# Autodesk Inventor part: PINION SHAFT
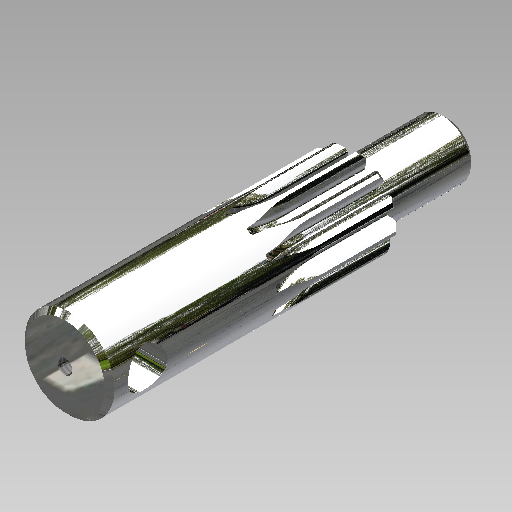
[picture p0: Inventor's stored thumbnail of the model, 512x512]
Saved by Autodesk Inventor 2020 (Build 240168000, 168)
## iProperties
Part Number: PINION SHAFT
Document SubType Name: Modeling
Created: 2003-10
Designer: Autodesk, Inc.
Manufacturer: Standard
Standards Organization: Custom
Mass: 507.092 g
Surface Area: 152.229 cm^2
Volume: 64.5977 cm^3
Density: 7.85 g/cm^3
Material: Steel, High Strength Low Alloy
Appearance: Chrome - Polished
Control State: 0
Master: False
Checked Out: False
Shininess: 64.0
Length Units: 11269
Angle Units: 11279
Time Units: 11290
Mass Units: 11283
Length Display Precision: 3
Angle Display Precision: 2
Compacted: True
Density: 0.0
Volumn: 0.0
Area: 0.0
PropertySet Name: Model Information
Author: Autodesk, Inc.
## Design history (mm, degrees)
sketch "Sketch1" dims "d4" = 6.7945 (= Big_R), "d5" = 5.54567 (= 2 x little_r)
  geometry: L1 (0, 12.7)-(5.815, 12.7); L2 (5.815, 12.7)-(5.815, 14.817); L3 (5.815, 14.817)-(0, 14.817); L4 (0, 14.817)-(0, 12.7); L5 (-8.163, 9.729)-(5.815, 14.817); L6 (0, 0)-(0, 10.251); L7 (0, 11.934)-(0, 12.7); L8 (0, 11.934)-(0, 10.251); L9 (-0.191, 11.933)-(-0.184, 10.731); L10 (0, 0)-(1.934, 14.69); L11 (0, 0)-(-1.338, 10.163); L12 (0, 0)-(3.923, 9.471); L13 (3.273, 11.477)-(2.955, 10.318); L14 (-0.181, 10.249)-(-0.184, 10.731); A1 r 12.7 centre (0, 0) between (0, 12.7) and (-8.163, 9.729); A2 r 14.817 centre (0, 0) between (0, 14.817) and (1.934, 14.69); A3 r 11.934 centre (0, 0) between (0, 11.934) and (6.294, 10.14); A4 r 10.251 centre (0, 0) between (0, 10.251) and (-0.181, 10.249); A5 r 6.795 centre (6.294, 10.14) between (1.365, 14.817) and (0, 12.7); A6 r 2.773 centre (2.568, 11.654) between (0, 12.7) and (-0.191, 11.933); A7 r 10.251 centre (0, 0) between (-0.651, 10.23) and (-1.338, 10.163); A8 r 0.498 centre (-0.682, 10.728) between (-0.651, 10.23) and (-0.184, 10.731); A9 r 10.251 centre (0, 0) between (3.923, 9.471) and (3.276, 9.713); A10 r 0.498 centre (3.435, 10.186) between (2.955, 10.318) and (3.276, 9.713); A11 r 2.773 centre (0.536, 11.922) between (3.273, 11.477) and (3.287, 12.267); A12 r 6.795 centre (-3.455, 11.423) between (3.287, 12.267) and (2.516, 14.665); A13 r 14.879 centre (0, 0) between (2.516, 14.665) and (1.365, 14.817); 2 further points; 1 other entity
  constraints: 30 point on circle, 28 end point, 13 centre point, 9 coincident, 9 symmetric about line, 4 tangent, 3 point on line, 2 parallel, 2 vertical, 1 collinear, 1 horizontal, 1 perpendicular, 16 other
  dimensions: "d0" = 25.4 diameter of A1 (= Pitch_Diameter); "d1" = 2.11667 distance of L1.end L2.end (= Addendum); "d2" = 20 deg angle of L1 L5 (= Tooth_Form); "d3" = 4.56565 distance of L6.end L3.end (= Whole_Depth); "d6" = 7.5 deg angle of L10 L6 (= mirror_angle); "d7" = 7.5 deg angle of L11 L6 (= mirror_angle); "d8" = 0.49848 radius of A8 (= Root_Fillet)
extrude "Extrusion1" new body sketch "Sketch1" distance "d9" = 25.4; taper "d10" = 0 deg
pattern_circular "Circular Pattern1" dims angle "d13" = 360 deg
sketch "Sketch2"
  geometry: C1 r 14.879 at (0, 0); 1 further point
  constraints: 1 centre point, 1 coincident
  dimensions: "d14" = 29.758 diameter of C1
extrude "Extrusion2" join sketch "Sketch2" distance "d15" = 71.4502; taper "d16" = 0 deg
sketch "Sketch3"
  geometry: C1 r 9.5 at (0, 0); 1 further point
  constraints: 1 centre point, 1 coincident
  dimensions: "d17" = 18.9992 diameter of C1
extrude "Extrusion3" join sketch "Sketch3" distance "d18" = 30.1498; taper "d19" = 0 deg
chamfer "Chamfer1" distance "d20" = 1.5875; stored, may be unused: second distance "d21" = 2, angle "d67" = 45 deg
chamfer "Chamfer2" distance "d22" = 1.5875; stored, may be unused: second distance "d23" = 2, angle "d68" = 45 deg
workplane "Work Plane2"
sketch "Sketch4"
  geometry: L1 (-13.292, 96.85)-(13.292, 96.85) reference; L2 (0, 96.85)-(0, 65.832); C1 r 6.54 at (0, 84.15)
  constraints: 2 end point, 1 centre point, 1 midpoint, 1 perpendicular, 1 point on line
  dimensions: "d26" = 13.081 diameter of C1; "d27" = 12.7 distance from line of L1 C1.centre
extrude "Extrusion4" cut sketch "Sketch4" distance "d28" = 50.8; taper "d29" = 0 deg
workplane "Work Plane3"
sketch "Sketch10"
  geometry: L1 (-5.206, 9.385)-(-5.801, 10.429) reference; L2 (-3.273, 11.477)-(-2.955, 10.318) reference; L3 (-5.801, 10.429)-(-5.206, 9.385); L4 (-2.955, 10.318)-(-3.273, 11.477); L5 (-30.301, 30.745)-(3.482, 44.738); L6 (-8.59, 12.149)-(-2.517, 14.665); L7 (0.184, 10.731)-(0.191, 11.933) reference; L8 (2.904, 11.575)-(2.6, 10.413) reference; L9 (0.191, 11.933)-(0.184, 10.731); L10 (2.904, 11.575)-(2.6, 10.413); L11 (5.524, 9.201)-(6.131, 10.239) reference; L12 (8.303, 8.572)-(7.458, 7.718) reference; L13 (5.524, 9.201)-(6.131, 10.239); L14 (7.458, 7.718)-(8.303, 8.572); L15 (9.385, 5.206)-(10.429, 5.801) reference; L16 (11.477, 3.273)-(10.318, 2.955) reference; L17 (9.385, 5.206)-(10.429, 5.801); L18 (11.477, 3.273)-(10.318, 2.955); A1 r 6.795 centre (3.455, 11.423) between (-2.517, 14.665) and (-3.287, 12.267) reference; A2 r 14.879 centre (0, 0) between (-2.517, 14.665) and (-8.59, 12.149) reference; A3 r 6.795 centre (-10.52, 5.634) between (-6.35, 10.999) and (-8.59, 12.149) reference; A4 r 2.773 centre (-8.051, 8.809) between (-5.801, 10.429) and (-6.35, 10.999) reference; A5 r 0.498 centre (-4.773, 9.632) between (-5.206, 9.385) and (-4.552, 9.185) reference; A6 r 10.251 centre (0, 0) between (-3.276, 9.713) and (-4.552, 9.185) reference; A7 r 0.498 centre (-3.435, 10.186) between (-3.276, 9.713) and (-2.955, 10.318) reference; A8 r 2.773 centre (-0.536, 11.922) between (-3.287, 12.267) and (-3.273, 11.477) reference; A9 r 14.879 centre (0, 0) between (-2.517, 14.665) and (-8.59, 12.149); A10 r 6.795 centre (-10.52, 5.634) between (-6.35, 10.999) and (-8.59, 12.149); A11 r 2.773 centre (-8.051, 8.809) between (-5.801, 10.429) and (-6.35, 10.999); A12 r 0.498 centre (-4.773, 9.632) between (-5.206, 9.385) and (-4.552, 9.185); A13 r 10.251 centre (0, 0) between (-3.276, 9.713) and (-4.552, 9.185); A14 r 6.795 centre (3.455, 11.423) between (-2.517, 14.665) and (-3.287, 12.267); A15 r 2.773 centre (-0.536, 11.922) between (-3.287, 12.267) and (-3.273, 11.477); A16 r 0.498 centre (-3.435, 10.186) between (-3.276, 9.713) and (-2.955, 10.318); A17 r 10.251 centre (0, 0) between (-3.276, 9.713) and (-4.552, 9.185) reference; A18 r 6.795 centre (8.704, 8.165) between (5.153, 13.958) and (3.287, 12.267) reference; A19 r 14.879 centre (0, 0) between (5.153, 13.958) and (-1.365, 14.816) reference; A20 r 6.795 centre (-6.294, 10.14) between (0, 12.7) and (-1.365, 14.816) reference; A21 r 2.773 centre (-2.568, 11.654) between (0.191, 11.933) and (0, 12.7) reference; A22 r 0.498 centre (0.682, 10.728) between (0.184, 10.731) and (0.651, 10.23) reference; A23 r 10.251 centre (0, 0) between (2.019, 10.05) and (0.651, 10.23) reference; A24 r 0.498 centre (2.118, 10.539) between (2.019, 10.05) and (2.6, 10.413) reference; A25 r 2.773 centre (5.497, 10.593) between (3.287, 12.267) and (2.904, 11.575) reference; A26 r 6.795 centre (-6.294, 10.14) between (0, 12.7) and (-1.365, 14.816); A27 r 2.773 centre (-2.568, 11.654) between (0.191, 11.933) and (0, 12.7); A28 r 0.498 centre (0.682, 10.728) between (0.184, 10.731) and (0.651, 10.23); A29 r 0.498 centre (2.118, 10.539) between (2.019, 10.05) and (2.6, 10.413); A30 r 2.773 centre (5.497, 10.593) between (3.287, 12.267) and (2.904, 11.575); A31 r 6.795 centre (8.704, 8.165) between (5.153, 13.958) and (3.287, 12.267); A32 r 14.879 centre (0, 0) between (5.153, 13.958) and (-1.365, 14.816); A33 r 10.251 centre (0, 0) between (2.019, 10.05) and (0.651, 10.23); A34 r 6.795 centre (11.62, 2.72) between (11.442, 9.512) and (8.98, 8.98) reference; A35 r 14.879 centre (0, 0) between (11.442, 9.512) and (6.226, 13.514) reference; A36 r 6.795 centre (-0.381, 11.928) between (6.35, 10.999) and (6.226, 13.514) reference; A37 r 2.773 centre (3.603, 11.377) between (6.131, 10.239) and (6.35, 10.999) reference; A38 r 0.498 centre (5.955, 8.949) between (5.524, 9.201) and (5.679, 8.534) reference; A39 r 10.251 centre (0, 0) between (6.774, 7.694) and (5.679, 8.534) reference; A40 r 0.498 centre (7.103, 8.068) between (6.774, 7.694) and (7.458, 7.718) reference; A41 r 2.773 centre (10.057, 6.425) between (8.98, 8.98) and (8.303, 8.572) reference; A42 r 14.879 centre (0, 0) between (11.442, 9.512) and (6.226, 13.514); A43 r 6.795 centre (-0.381, 11.928) between (6.35, 10.999) and (6.226, 13.514); A44 r 2.773 centre (3.603, 11.377) between (6.131, 10.239) and (6.35, 10.999); A45 r 0.498 centre (5.955, 8.949) between (5.524, 9.201) and (5.679, 8.534); A46 r 0.498 centre (7.103, 8.068) between (6.774, 7.694) and (7.458, 7.718); A47 r 2.773 centre (10.057, 6.425) between (8.98, 8.98) and (8.303, 8.572); A48 r 6.795 centre (11.62, 2.72) between (11.442, 9.512) and (8.98, 8.98); A49 r 10.251 centre (0, 0) between (6.774, 7.694) and (5.679, 8.534); A50 r 6.795 centre (11.423, -3.455) between (14.665, 2.517) and (12.267, 3.287) reference; A51 r 14.879 centre (0, 0) between (14.665, 2.517) and (12.149, 8.59) reference; A52 r 6.795 centre (5.634, 10.52) between (10.999, 6.35) and (12.149, 8.59) reference; A53 r 2.773 centre (8.809, 8.051) between (10.429, 5.801) and (10.999, 6.35) reference; A54 r 0.498 centre (9.632, 4.773) between (9.385, 5.206) and (9.185, 4.552) reference; A55 r 10.251 centre (0, 0) between (9.713, 3.276) and (9.185, 4.552) reference; A56 r 0.498 centre (10.186, 3.435) between (9.713, 3.276) and (10.318, 2.955) reference; A57 r 2.773 centre (11.922, 0.536) between (12.267, 3.287) and (11.477, 3.273) reference; A58 r 10.251 centre (0, 0) between (9.713, 3.276) and (9.185, 4.552); A59 r 0.498 centre (9.632, 4.773) between (9.385, 5.206) and (9.185, 4.552); A60 r 0.498 centre (10.186, 3.435) between (9.713, 3.276) and (10.318, 2.955); A61 r 2.773 centre (11.922, 0.536) between (12.267, 3.287) and (11.477, 3.273); A62 r 2.773 centre (8.809, 8.051) between (10.429, 5.801) and (10.999, 6.35); A63 r 6.795 centre (5.634, 10.52) between (10.999, 6.35) and (12.149, 8.59); A64 r 6.794 centre (11.423, -3.455) between (14.665, 2.517) and (12.267, 3.287)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
  constraints: 66 point on circle, 32 centre point, 30 concentric, 27 tangent, 20 end point, 8 collinear, 1 parallel
  dimensions: "d32" = 40 distance from line of L5 A17.centre
revolve "Revolution1" sketch "Sketch10" stored, may be unused: angle "d33" = 90 deg
sketch "Sketch11"
  geometry: L1 (0.184, 10.731)-(0.191, 11.933) reference; L2 (2.904, 11.575)-(2.6, 10.413) reference; L3 (0.184, 10.731)-(0.191, 11.933); L4 (2.6, 10.413)-(2.904, 11.575); L5 (-8.56, 41.472)-(25.088, 37.042); L6 (-1.365, 14.816)-(5.153, 13.958); C1 r 7.912 at (0, 0) reference; A1 r 6.795 centre (8.704, 8.165) between (5.153, 13.958) and (3.287, 12.267) reference; A2 r 14.879 centre (0, 0) between (5.153, 13.958) and (-1.365, 14.816) reference; A3 r 6.795 centre (-6.294, 10.14) between (0, 12.7) and (-1.365, 14.816) reference; A4 r 2.773 centre (-2.568, 11.654) between (0.191, 11.933) and (0, 12.7) reference; A5 r 0.498 centre (0.682, 10.728) between (0.184, 10.731) and (0.651, 10.23) reference; A6 r 10.251 centre (0, 0) between (2.019, 10.05) and (0.651, 10.23) reference; A7 r 0.498 centre (2.118, 10.539) between (2.019, 10.05) and (2.6, 10.413) reference; A8 r 2.773 centre (5.497, 10.593) between (3.287, 12.267) and (2.904, 11.575) reference; A9 r 14.879 centre (0, 0) between (5.153, 13.958) and (-1.365, 14.816); A10 r 6.795 centre (-6.294, 10.14) between (0, 12.7) and (-1.365, 14.816); A11 r 2.773 centre (-2.568, 11.654) between (0.191, 11.933) and (0, 12.7); A12 r 0.498 centre (0.682, 10.728) between (0.184, 10.731) and (0.651, 10.23); A13 r 10.251 centre (0, 0) between (2.019, 10.05) and (0.651, 10.23); A14 r 6.795 centre (8.704, 8.165) between (5.153, 13.958) and (3.287, 12.267); A15 r 2.773 centre (5.497, 10.593) between (3.287, 12.267) and (2.904, 11.575); A16 r 0.498 centre (2.118, 10.539) between (2.019, 10.05) and (2.6, 10.413)
  constraints: 16 point on circle, 8 centre point, 8 end point, 8 tangent, 6 concentric, 2 collinear, 1 parallel
  dimensions: "d35" = 40 distance from line of C1.centre L5
revolve "Revolution2" sketch "Sketch11" stored, may be unused: angle "d36" = 90 deg
sketch "Sketch12"
  geometry: L1 (5.524, 9.201)-(6.131, 10.239) reference; L2 (8.303, 8.572)-(7.458, 7.718) reference; L3 (8.303, 8.572)-(7.458, 7.718); L4 (5.524, 9.201)-(6.131, 10.239); L5 (37.465, 21.671)-(7.155, 44.928); L6 (11.442, 9.512)-(6.226, 13.514); C1 r 7.912 at (0, 0) reference; A1 r 6.795 centre (11.62, 2.72) between (11.442, 9.512) and (8.98, 8.98) reference; A2 r 14.879 centre (0, 0) between (11.442, 9.512) and (6.226, 13.514) reference; A3 r 6.795 centre (-0.381, 11.928) between (6.35, 10.999) and (6.226, 13.514) reference; A4 r 2.773 centre (3.603, 11.377) between (6.131, 10.239) and (6.35, 10.999) reference; A5 r 0.498 centre (5.955, 8.949) between (5.524, 9.201) and (5.679, 8.534) reference; A6 r 10.251 centre (0, 0) between (6.774, 7.694) and (5.679, 8.534) reference; A7 r 0.498 centre (7.103, 8.068) between (6.774, 7.694) and (7.458, 7.718) reference; A8 r 2.773 centre (10.057, 6.425) between (8.98, 8.98) and (8.303, 8.572) reference; A9 r 14.879 centre (0, 0) between (11.442, 9.512) and (6.226, 13.514); A10 r 0.498 centre (5.955, 8.949) between (5.524, 9.201) and (5.679, 8.534); A11 r 6.795 centre (-0.381, 11.928) between (6.35, 10.999) and (6.226, 13.514); A12 r 2.773 centre (3.603, 11.377) between (6.131, 10.239) and (6.35, 10.999); A13 r 0.498 centre (7.103, 8.068) between (6.774, 7.694) and (7.458, 7.718); A14 r 2.773 centre (10.057, 6.425) between (8.98, 8.98) and (8.303, 8.572); A15 r 6.795 centre (11.62, 2.72) between (11.442, 9.512) and (8.98, 8.98); A16 r 10.251 centre (0, 0) between (6.774, 7.694) and (5.679, 8.534)
  constraints: 16 point on circle, 8 centre point, 8 end point, 7 concentric, 7 tangent, 2 collinear, 1 parallel
  dimensions: "d37" = 40 distance from line of C1.centre L5
revolve "Revolution3" sketch "Sketch12" stored, may be unused: angle "d38" = 90 deg
sketch "Sketch13"
  geometry: L1 (9.385, 5.206)-(10.429, 5.801) reference; L2 (11.477, 3.273)-(10.318, 2.955) reference; L3 (9.385, 5.206)-(10.429, 5.801); L4 (10.318, 2.955)-(11.477, 3.273); L5 (14.665, 2.517)-(12.149, 8.59); L6 (43.302, -0.015)-(26.182, 41.316); C1 r 7.912 at (0, 0) reference; A1 r 6.795 centre (11.423, -3.455) between (14.665, 2.517) and (12.267, 3.287) reference; A2 r 14.879 centre (0, 0) between (14.665, 2.517) and (12.149, 8.59) reference; A3 r 6.795 centre (5.634, 10.52) between (10.999, 6.35) and (12.149, 8.59) reference; A4 r 2.773 centre (8.809, 8.051) between (10.429, 5.801) and (10.999, 6.35) reference; A5 r 0.498 centre (9.632, 4.773) between (9.385, 5.206) and (9.185, 4.552) reference; A6 r 10.251 centre (0, 0) between (9.713, 3.276) and (9.185, 4.552) reference; A7 r 0.498 centre (10.186, 3.435) between (9.713, 3.276) and (10.318, 2.955) reference; A8 r 2.773 centre (11.922, 0.536) between (12.267, 3.287) and (11.477, 3.273) reference; A9 r 6.795 centre (5.634, 10.52) between (10.999, 6.35) and (12.149, 8.59); A10 r 2.773 centre (8.809, 8.051) between (10.429, 5.801) and (10.999, 6.35); A11 r 0.498 centre (9.632, 4.773) between (9.385, 5.206) and (9.185, 4.552); A12 r 0.498 centre (10.186, 3.435) between (9.713, 3.276) and (10.318, 2.955); A13 r 2.773 centre (11.922, 0.536) between (12.267, 3.287) and (11.477, 3.273); A14 r 10.251 centre (0, 0) between (9.713, 3.276) and (9.185, 4.552); A15 r 6.795 centre (11.423, -3.455) between (14.665, 2.517) and (12.267, 3.287); A16 r 14.879 centre (0, 0) between (14.665, 2.517) and (12.149, 8.59)
  constraints: 16 point on circle, 8 centre point, 8 concentric, 8 end point, 2 collinear, 2 tangent, 1 parallel
  dimensions: "d39" = 40 distance from line of C1.centre L6
  node "Projected Loop8"
sketch "Sketch14"
  geometry: L1 (-9.201, 5.524)-(-10.239, 6.131) reference; L2 (-8.572, 8.303)-(-7.718, 7.458) reference; L3 (-9.201, 5.524)-(-10.239, 6.131); L4 (-7.718, 7.458)-(-8.572, 8.303); L5 (-13.514, 6.226)-(-9.512, 11.442); L6 (-43.85, 8.561)-(-20.3, 39.252); C1 r 7.912 at (0, 0) reference; A1 r 6.795 centre (-11.928, -0.381) between (-10.999, 6.35) and (-13.514, 6.226) reference; A2 r 2.773 centre (-11.377, 3.603) between (-10.239, 6.131) and (-10.999, 6.35) reference; A3 r 0.498 centre (-8.949, 5.955) between (-9.201, 5.524) and (-8.534, 5.679) reference; A4 r 10.251 centre (0, 0) between (-7.694, 6.774) and (-8.534, 5.679) reference; A5 r 0.498 centre (-8.068, 7.103) between (-7.694, 6.774) and (-7.718, 7.458) reference; A6 r 2.773 centre (-6.425, 10.057) between (-8.98, 8.98) and (-8.572, 8.303) reference; A7 r 6.795 centre (-2.72, 11.62) between (-9.512, 11.442) and (-8.98, 8.98) reference; A8 r 14.879 centre (0, 0) between (-9.512, 11.442) and (-13.514, 6.226) reference; A9 r 14.879 centre (0, 0) between (-9.512, 11.442) and (-13.514, 6.226); A10 r 0.498 centre (-8.949, 5.955) between (-9.201, 5.524) and (-8.534, 5.679); A11 r 2.773 centre (-11.377, 3.603) between (-10.239, 6.131) and (-10.999, 6.35); A12 r 6.795 centre (-11.928, -0.381) between (-10.999, 6.35) and (-13.514, 6.226); A13 r 6.795 centre (-2.72, 11.62) between (-9.512, 11.442) and (-8.98, 8.98); A14 r 2.773 centre (-6.425, 10.057) between (-8.98, 8.98) and (-8.572, 8.303); A15 r 10.251 centre (0, 0) between (-7.694, 6.774) and (-8.534, 5.679); A16 r 0.498 centre (-8.068, 7.103) between (-7.694, 6.774) and (-7.718, 7.458)
  constraints: 17 point on circle, 8 centre point, 8 end point, 8 tangent, 6 concentric, 2 collinear, 1 parallel
  dimensions: "d40" = 40 distance from line of C1.centre L6
revolve "Revolution5" sketch "Sketch14" stored, may be unused: angle "d42" = 90 deg
revolve "Revolution6" stored, may be unused: angle "d43" = 90 deg
sketch "Sketch15"
  geometry: L1 (10.731, -0.184)-(11.933, -0.191) reference; L2 (11.575, -2.904)-(10.413, -2.6) reference; L3 (10.731, -0.184)-(11.933, -0.191); L4 (10.413, -2.6)-(11.575, -2.904); L5 (13.958, -5.153)-(14.816, 1.365); L6 (42.416, 15.732)-(37.273, -23.332); C1 r 7.912 at (0, 0) reference; A1 r 6.795 centre (8.165, -8.704) between (13.958, -5.153) and (12.267, -3.287) reference; A2 r 14.879 centre (0, 0) between (13.958, -5.153) and (14.816, 1.365) reference; A3 r 6.795 centre (10.14, 6.294) between (12.7, 0) and (14.816, 1.365) reference; A4 r 2.773 centre (11.654, 2.568) between (11.933, -0.191) and (12.7, 0) reference; A5 r 0.498 centre (10.728, -0.682) between (10.731, -0.184) and (10.23, -0.651) reference; A6 r 10.251 centre (0, 0) between (10.05, -2.019) and (10.23, -0.651) reference; A7 r 0.498 centre (10.539, -2.118) between (10.05, -2.019) and (10.413, -2.6) reference; A8 r 2.773 centre (10.593, -5.497) between (12.267, -3.287) and (11.575, -2.904) reference; A9 r 14.879 centre (0, 0) between (13.958, -5.153) and (14.816, 1.365); A10 r 6.795 centre (10.14, 6.294) between (12.7, 0) and (14.816, 1.365); A11 r 2.773 centre (11.654, 2.568) between (11.933, -0.191) and (12.7, 0); A12 r 0.498 centre (10.728, -0.682) between (10.731, -0.184) and (10.23, -0.651); A13 r 10.251 centre (0, 0) between (10.05, -2.019) and (10.23, -0.651); A14 r 0.498 centre (10.539, -2.118) between (10.05, -2.019) and (10.413, -2.6); A15 r 2.773 centre (10.593, -5.497) between (12.267, -3.287) and (11.575, -2.904); A16 r 6.795 centre (8.165, -8.704) between (13.958, -5.153) and (12.267, -3.287)
  constraints: 16 point on circle, 8 centre point, 8 concentric, 8 end point, 5 tangent, 2 collinear, 1 parallel
  dimensions: "d44" = 40 distance from line of C1.centre L6
revolve "Revolution7" sketch "Sketch15" stored, may be unused: angle "d45" = 90 deg
sketch "Sketch16"
  geometry: L1 (9.201, -5.524)-(10.239, -6.131) reference; L2 (8.572, -8.303)-(7.718, -7.458) reference; L3 (9.201, -5.524)-(10.239, -6.131); L4 (7.718, -7.458)-(8.572, -8.303); L5 (9.512, -11.442)-(13.514, -6.226); L6 (22.205, -36.769)-(41.695, -11.369); C1 r 7.912 at (0, 0) reference; A1 r 6.795 centre (2.72, -11.62) between (9.512, -11.442) and (8.98, -8.98) reference; A2 r 14.879 centre (0, 0) between (9.512, -11.442) and (13.514, -6.226) reference; A3 r 6.795 centre (11.928, 0.381) between (10.999, -6.35) and (13.514, -6.226) reference; A4 r 2.773 centre (11.377, -3.603) between (10.239, -6.131) and (10.999, -6.35) reference; A5 r 0.498 centre (8.949, -5.955) between (9.201, -5.524) and (8.534, -5.679) reference; A6 r 10.251 centre (0, 0) between (7.694, -6.774) and (8.534, -5.679) reference; A7 r 0.498 centre (8.068, -7.103) between (7.694, -6.774) and (7.718, -7.458) reference; A8 r 2.773 centre (6.425, -10.057) between (8.98, -8.98) and (8.572, -8.303) reference; A9 r 14.879 centre (0, 0) between (9.512, -11.442) and (13.514, -6.226); A10 r 6.795 centre (11.928, 0.381) between (10.999, -6.35) and (13.514, -6.226); A11 r 2.773 centre (11.377, -3.603) between (10.239, -6.131) and (10.999, -6.35); A12 r 0.498 centre (8.949, -5.955) between (9.201, -5.524) and (8.534, -5.679); A13 r 0.498 centre (8.068, -7.103) between (7.694, -6.774) and (7.718, -7.458); A14 r 2.773 centre (6.425, -10.057) between (8.98, -8.98) and (8.572, -8.303); A15 r 6.795 centre (2.72, -11.62) between (9.512, -11.442) and (8.98, -8.98); A16 r 10.251 centre (0, 0) between (7.694, -6.774) and (8.534, -5.679)
  constraints: 18 point on circle, 9 tangent, 8 centre point, 8 end point, 6 concentric, 2 collinear, 1 parallel
  dimensions: "d51" = 40 distance from line of C1.centre L6
revolve "Revolution8" sketch "Sketch16" stored, may be unused: angle "d48" = 90 deg
sketch "Sketch17"
  geometry: L1 (5.206, -9.385)-(5.801, -10.429) reference; L2 (3.273, -11.477)-(2.955, -10.318) reference; L3 (5.206, -9.385)-(5.801, -10.429); L4 (2.955, -10.318)-(3.273, -11.477); L5 (8.59, -12.149)-(2.517, -14.665); L6 (-1.988, -44.119)-(32.429, -29.863); C1 r 7.912 at (0, 0) reference; A1 r 6.795 centre (10.52, -5.634) between (6.35, -10.999) and (8.59, -12.149) reference; A2 r 2.773 centre (8.051, -8.809) between (5.801, -10.429) and (6.35, -10.999) reference; A3 r 0.498 centre (4.773, -9.632) between (5.206, -9.385) and (4.552, -9.185) reference; A4 r 10.251 centre (0, 0) between (3.276, -9.713) and (4.552, -9.185) reference; A5 r 0.498 centre (3.435, -10.186) between (3.276, -9.713) and (2.955, -10.318) reference; A6 r 2.773 centre (0.536, -11.922) between (3.287, -12.267) and (3.273, -11.477) reference; A7 r 6.795 centre (-3.455, -11.423) between (2.517, -14.665) and (3.287, -12.267) reference; A8 r 14.879 centre (0, 0) between (2.517, -14.665) and (8.59, -12.149) reference; A9 r 14.879 centre (0, 0) between (2.517, -14.665) and (8.59, -12.149); A10 r 6.795 centre (-3.455, -11.423) between (2.517, -14.665) and (3.287, -12.267); A11 r 2.773 centre (0.536, -11.922) between (3.287, -12.267) and (3.273, -11.477); A12 r 0.498 centre (3.435, -10.186) between (3.276, -9.713) and (2.955, -10.318); A13 r 0.498 centre (4.773, -9.632) between (5.206, -9.385) and (4.552, -9.185); A14 r 6.795 centre (10.52, -5.634) between (6.35, -10.999) and (8.59, -12.149); A15 r 2.773 centre (8.051, -8.809) between (5.801, -10.429) and (6.35, -10.999); A16 r 10.251 centre (0, 0) between (3.276, -9.713) and (4.552, -9.185)
  constraints: 17 point on circle, 8 centre point, 8 end point, 7 concentric, 5 tangent, 2 collinear, 1 parallel
  dimensions: "d49" = 40 distance from line of C1.centre L6
revolve "Revolution9" sketch "Sketch17" stored, may be unused: angle "d50" = 90 deg
sketch "Sketch18"
  geometry: L1 (-0.184, -10.731)-(-0.191, -11.933) reference; L2 (-2.904, -11.575)-(-2.6, -10.413) reference; L3 (-0.184, -10.731)-(-0.191, -11.933); L4 (-2.6, -10.413)-(-2.904, -11.575); L5 (-5.153, -13.958)-(1.365, -14.816); L6 (18.309, -42.756)-(-25.099, -37.041); C1 r 7.912 at (0, 0) reference; A1 r 6.795 centre (6.294, -10.14) between (0, -12.7) and (1.365, -14.816) reference; A2 r 2.773 centre (2.568, -11.654) between (-0.191, -11.933) and (0, -12.7) reference; A3 r 0.498 centre (-0.682, -10.728) between (-0.184, -10.731) and (-0.651, -10.23) reference; A4 r 10.251 centre (0, 0) between (-2.019, -10.05) and (-0.651, -10.23) reference; A5 r 0.498 centre (-2.118, -10.539) between (-2.019, -10.05) and (-2.6, -10.413) reference; A6 r 2.773 centre (-5.497, -10.593) between (-3.287, -12.267) and (-2.904, -11.575) reference; A7 r 6.795 centre (-8.704, -8.165) between (-5.153, -13.958) and (-3.287, -12.267) reference; A8 r 14.879 centre (0, 0) between (-5.153, -13.958) and (1.365, -14.816) reference; A9 r 14.879 centre (0, 0) between (-5.153, -13.958) and (1.365, -14.816); A10 r 6.795 centre (6.294, -10.14) between (0, -12.7) and (1.365, -14.816); A11 r 0.498 centre (-0.682, -10.728) between (-0.184, -10.731) and (-0.651, -10.23); A12 r 2.773 centre (2.568, -11.654) between (-0.191, -11.933) and (0, -12.7); A13 r 6.795 centre (-8.704, -8.165) between (-5.153, -13.958) and (-3.287, -12.267); A14 r 2.773 centre (-5.497, -10.593) between (-3.287, -12.267) and (-2.904, -11.575); A15 r 0.498 centre (-2.118, -10.539) between (-2.019, -10.05) and (-2.6, -10.413); A16 r 10.251 centre (0, 0) between (-2.019, -10.05) and (-0.651, -10.23)
  constraints: 16 point on circle, 9 tangent, 8 centre point, 8 end point, 6 concentric, 2 collinear, 1 parallel
  dimensions: "d52" = 40 distance from line of L6 C1.centre
revolve "Revolution10" sketch "Sketch18" stored, may be unused: angle "d53" = 90 deg
sketch "Sketch19"
  geometry: L1 (-5.524, -9.201)-(-6.131, -10.239) reference; L2 (-8.303, -8.572)-(-7.458, -7.718) reference; L3 (-5.524, -9.201)-(-6.131, -10.239); L4 (-7.458, -7.718)-(-8.303, -8.572); L5 (-11.442, -9.512)-(-6.226, -13.514); L6 (-14.257, -39.479)-(-36.918, -22.091); C1 r 7.912 at (0, 0) reference; A1 r 6.795 centre (0.381, -11.928) between (-6.35, -10.999) and (-6.226, -13.514) reference; A2 r 2.773 centre (-3.603, -11.377) between (-6.131, -10.239) and (-6.35, -10.999) reference; A3 r 0.498 centre (-5.955, -8.949) between (-5.524, -9.201) and (-5.679, -8.534) reference; A4 r 10.251 centre (0, 0) between (-6.774, -7.694) and (-5.679, -8.534) reference; A5 r 0.498 centre (-7.103, -8.068) between (-6.774, -7.694) and (-7.458, -7.718) reference; A6 r 2.773 centre (-10.057, -6.425) between (-8.98, -8.98) and (-8.303, -8.572) reference; A7 r 6.795 centre (-11.62, -2.72) between (-11.442, -9.512) and (-8.98, -8.98) reference; A8 r 14.879 centre (0, 0) between (-11.442, -9.512) and (-6.226, -13.514) reference; A9 r 14.879 centre (0, 0) between (-11.442, -9.512) and (-6.226, -13.514); A10 r 6.795 centre (0.381, -11.928) between (-6.35, -10.999) and (-6.226, -13.514); A11 r 0.498 centre (-5.955, -8.949) between (-5.524, -9.201) and (-5.679, -8.534); A12 r 0.498 centre (-7.103, -8.068) between (-6.774, -7.694) and (-7.458, -7.718); A13 r 6.795 centre (-11.62, -2.72) between (-11.442, -9.512) and (-8.98, -8.98); A14 r 10.251 centre (0, 0) between (-6.774, -7.694) and (-5.679, -8.534); A15 r 2.773 centre (-10.057, -6.425) between (-8.98, -8.98) and (-8.303, -8.572); A16 r 2.773 centre (-3.603, -11.377) between (-6.131, -10.239) and (-6.35, -10.999)
  constraints: 16 point on circle, 11 tangent, 8 centre point, 8 end point, 5 concentric, 2 collinear, 1 parallel
  dimensions: "d54" = 40 distance from line of C1.centre L6
revolve "Revolution11" sketch "Sketch19" stored, may be unused: angle "d55" = 90 deg
sketch "Sketch20"
  geometry: L1 (-9.385, -5.206)-(-10.429, -5.801) reference; L2 (-11.477, -3.273)-(-10.318, -2.955) reference; L3 (-9.385, -5.206)-(-10.429, -5.801); L4 (-10.318, -2.955)-(-11.477, -3.273); L5 (-14.665, -2.517)-(-12.149, -8.59); L6 (-31.542, -28.377)-(-43.268, -0.067); C1 r 7.912 at (0, 0) reference; A1 r 6.795 centre (-5.634, -10.52) between (-10.999, -6.35) and (-12.149, -8.59) reference; A2 r 2.773 centre (-8.809, -8.051) between (-10.429, -5.801) and (-10.999, -6.35) reference; A3 r 0.498 centre (-9.632, -4.773) between (-9.385, -5.206) and (-9.185, -4.552) reference; A4 r 10.251 centre (0, 0) between (-9.713, -3.276) and (-9.185, -4.552) reference; A5 r 0.498 centre (-10.186, -3.435) between (-9.713, -3.276) and (-10.318, -2.955) reference; A6 r 2.773 centre (-11.922, -0.536) between (-12.267, -3.287) and (-11.477, -3.273) reference; A7 r 6.795 centre (-11.423, 3.455) between (-14.665, -2.517) and (-12.267, -3.287) reference; A8 r 14.879 centre (0, 0) between (-14.665, -2.517) and (-12.149, -8.59) reference; A9 r 14.879 centre (0, 0) between (-14.665, -2.517) and (-12.149, -8.59); A10 r 6.795 centre (-11.423, 3.455) between (-14.665, -2.517) and (-12.267, -3.287); A11 r 6.795 centre (-5.634, -10.52) between (-10.999, -6.35) and (-12.149, -8.59); A12 r 0.498 centre (-9.632, -4.773) between (-9.385, -5.206) and (-9.185, -4.552); A13 r 0.498 centre (-10.186, -3.435) between (-9.713, -3.276) and (-10.318, -2.955); A14 r 2.773 centre (-11.922, -0.536) between (-12.267, -3.287) and (-11.477, -3.273); A15 r 2.773 centre (-8.809, -8.051) between (-10.429, -5.801) and (-10.999, -6.35); A16 r 10.251 centre (0, 0) between (-9.713, -3.276) and (-9.185, -4.552)
  constraints: 16 point on circle, 8 centre point, 8 end point, 7 concentric, 7 tangent, 2 collinear, 1 parallel
  dimensions: "d56" = 40 distance from line of C1.centre L6
revolve "Revolution12" sketch "Sketch20" stored, may be unused: angle "d57" = 90 deg
sketch "Sketch21"
  geometry: L1 (-10.731, 0.184)-(-11.933, 0.191) reference; L2 (-11.575, 2.904)-(-10.413, 2.6) reference; L3 (-10.731, 0.184)-(-11.933, 0.191); L4 (-10.413, 2.6)-(-11.575, 2.904); L5 (-13.958, 5.153)-(-14.816, -1.365); L6 (-37.606, 20.805)-(-41.538, -9.057); C1 r 7.912 at (0, 0) reference; A1 r 6.795 centre (-10.14, -6.294) between (-12.7, 0) and (-14.816, -1.365) reference; A2 r 2.773 centre (-11.654, -2.568) between (-11.933, 0.191) and (-12.7, 0) reference; A3 r 0.498 centre (-10.728, 0.682) between (-10.731, 0.184) and (-10.23, 0.651) reference; A4 r 10.251 centre (0, 0) between (-10.05, 2.019) and (-10.23, 0.651) reference; A5 r 0.498 centre (-10.539, 2.118) between (-10.05, 2.019) and (-10.413, 2.6) reference; A6 r 2.773 centre (-10.593, 5.497) between (-12.267, 3.287) and (-11.575, 2.904) reference; A7 r 6.795 centre (-8.165, 8.704) between (-13.958, 5.153) and (-12.267, 3.287) reference; A8 r 14.879 centre (0, 0) between (-13.958, 5.153) and (-14.816, -1.365) reference; A9 r 14.879 centre (0, 0) between (-13.958, 5.153) and (-14.816, -1.365); A10 r 6.795 centre (-10.14, -6.294) between (-12.7, 0) and (-14.816, -1.365); A11 r 0.498 centre (-10.728, 0.682) between (-10.731, 0.184) and (-10.23, 0.651); A12 r 0.498 centre (-10.539, 2.118) between (-10.05, 2.019) and (-10.413, 2.6); A13 r 2.773 centre (-10.593, 5.497) between (-12.267, 3.287) and (-11.575, 2.904); A14 r 2.773 centre (-11.654, -2.568) between (-11.933, 0.191) and (-12.7, 0); A15 r 6.795 centre (-8.165, 8.704) between (-13.958, 5.153) and (-12.267, 3.287); A16 r 10.251 centre (0, 0) between (-10.05, 2.019) and (-10.23, 0.651)
  constraints: 16 point on circle, 8 centre point, 8 end point, 6 concentric, 6 tangent, 2 collinear, 1 parallel
  dimensions: "d58" = 40 distance from line of C1.centre L6
revolve "Revolution13" sketch "Sketch21" stored, may be unused: angle "d59" = 90 deg
sketch "Sketch22"
  geometry: C1 r 13.292 at (0, 0) reference; 1 further point
  constraints: 1 coincident
hole "Hole1" sketch "Sketch22" at (0, 0) diameter "d60" = 4.978; stored, may be unused: countersink angle "d64" = 82 deg, drill point angle "d66" = 118 deg; dims "d61" = 6, "d62" = 4, "d63" = 2, "d65" = 8
body "Solid1"
node "Projected Loop2"
node "Projected Loop3"
node "Projected Loop4"
node "Projected Loop5"
node "Projected Loop6"
node "Projected Loop7"
node "Projected Loop9"
node "Projected Loop10"
node "Projected Loop11"
node "Projected Loop12"
node "Projected Loop13"
node "Projected Loop14"
node "Projected Loop15"
node "Projected Loop16"
node "Projected Loop17"
other parameters: "Tooth_Form" = 20 deg [user parameter; used in 1 equation term], "Pitch_Diameter" = 25.4 [user parameter; used in 1 equation term], "Addendum" = 2.11667 [user parameter; used in 1 equation term], "Whole_Depth" = 4.56565 [user parameter; used in 1 equation term], "Big_R" = 6.7945 [user parameter; used in 1 equation term], "little_r" = 2.77283 [user parameter; used in 1 equation term], "Root_Fillet" = 0.49848 [user parameter; used in 1 equation term], "mirror_angle" = 7.5 deg [user parameter; used in 2 equation terms], "d25" = 16.75
